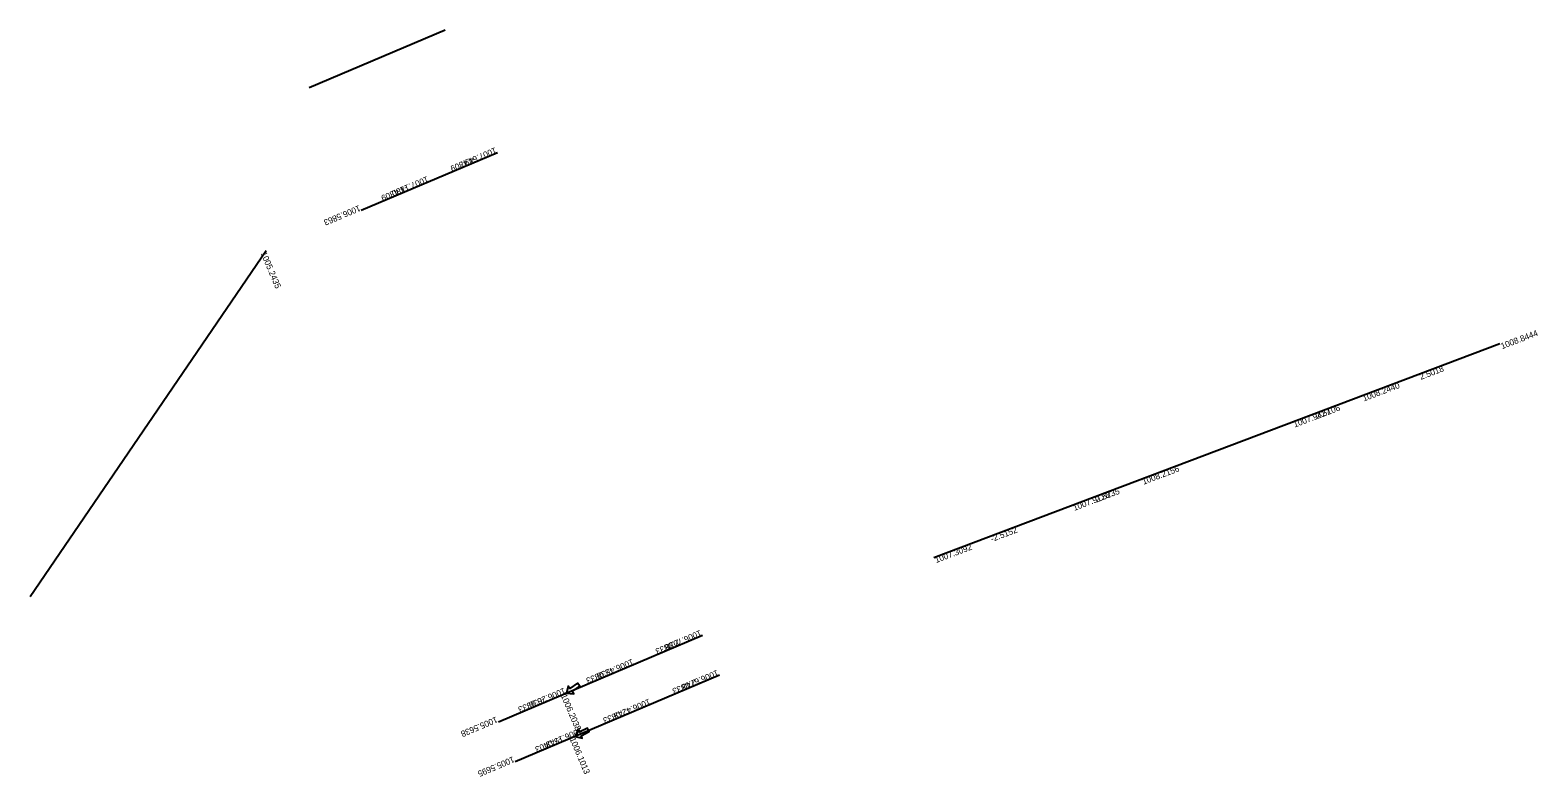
# Model space of a CAD drawing. Extents: x 2123 to 16973325, y 6087 to 12564921.
# Drawn here: x 1611395 to 1611639.8, y 1092704.5 to 1092825.8 of the extents above; entities that cross this region are included whole.
import ezdxf

# ---------------------------------------------------------------- set-up
doc = ezdxf.new("R2010")
doc.units = 0
doc.layers.add('Default', color=7, linetype='Continuous')
doc.layers.add('RD_PD_ConcMed', color=7, linetype='Continuous')

msp = doc.modelspace()

# ---------------------------------------------------------------- linework, layer by layer
at = {"layer": 'Default'}
for p, q in [((1611462.42, 1092825.84), (1611440.33, 1092816.46)), ((1611470.89, 1092805.9), (1611448.8, 1092796.52)), ((1611541.78, 1092740.18), (1611633.68, 1092774.94)), ((1611504.18, 1092727.5), (1611471.05, 1092713.43)), ((1611506.93, 1092721.03), (1611473.79, 1092706.96))]:
    msp.add_line(p, q, dxfattribs=at)
for points in [[(1611482.09, 1092718.12), (1611483.29, 1092718.02), (1611483.03, 1092718.38), (1611484.26, 1092719.25), (1611483.89, 1092719.77), (1611482.66, 1092718.91), (1611482.4, 1092719.28)], [(1611483.51, 1092711.08), (1611484.67, 1092710.8), (1611484.47, 1092711.21), (1611485.81, 1092711.88), (1611485.52, 1092712.46), (1611484.18, 1092711.78), (1611483.98, 1092712.18)]]:
    msp.add_lwpolyline(points, close=True, dxfattribs=at)
at = {"layer": 'RD_PD_ConcMed'}
msp.add_line((1611433.35, 1092789.96), (1611395.03, 1092733.77), dxfattribs=at)

# ---------------------------------------------------------------- texts
at = {"layer": 'Default'}
for s, rotation, p in [('4.4309', 203.0073, (1611466.91, 1092805.3)), ('1007.6497', 203.0073, (1611470.5, 1092806.83)), ('-4.4309', 203.0073, (1611456.08, 1092800.7)), ('1007.1180', 203.0073, (1611459.45, 1092802.14)), ('1006.5863', 203.0073, (1611448.41, 1092797.44)), ('1005.2435', 293.0073, (1611432.43, 1092789.57)), ('1008.8444', 20.7167, (1611634.03, 1092774)), ('2.5018', 20.7167, (1611620.84, 1092769.01)), ('1008.2440', 20.7167, (1611611.59, 1092765.51)), ('1007.9427', 20.7167, (1611600.36, 1092761.27)), ('2.5106', 20.7167, (1611604.01, 1092762.65)), ('1008.2156', 20.7167, (1611575.81, 1092751.98)), ('2.5235', 20.7167, (1611568.22, 1092749.11)), ('1007.9128', 20.7167, (1611564.58, 1092747.74)), ('-2.5152', 20.7167, (1611551.18, 1092742.67)), ('1007.3092', 20.7167, (1611542.14, 1092739.25)), ('2.0833', 203.0073, (1611500.21, 1092726.9)), ('1006.7038', 203.0073, (1611503.79, 1092728.42)), ('-2.0833', 203.0073, (1611489.37, 1092722.3)), ('1006.4538', 203.0073, (1611492.75, 1092723.73)), ('1006.6743', 203.0073, (1611506.54, 1092721.95)), ('2.0833', 203.0073, (1611502.95, 1092720.42)), ('-5.3333', 203.0073, (1611478.33, 1092717.61)), ('1006.2038', 203.0073, (1611481.7, 1092719.04)), ('1006.2038', 293.0073, (1611481.17, 1092717.73)), ('1006.4243', 203.0073, (1611495.49, 1092717.26)), ('1005.5638', 203.0073, (1611470.66, 1092714.35)), ('-2.0833', 203.0073, (1611492.12, 1092715.82)), ('1006.1743', 203.0073, (1611484.45, 1092712.57)), ('-5.0403', 203.0073, (1611481.08, 1092711.13)), ('1006.1013', 293.0073, (1611482.59, 1092710.69)), ('1005.5695', 203.0073, (1611473.4, 1092707.88))]:
    msp.add_text(s, height=1, rotation=rotation, dxfattribs=at).set_placement(p)

doc.saveas('drawing.dxf')
